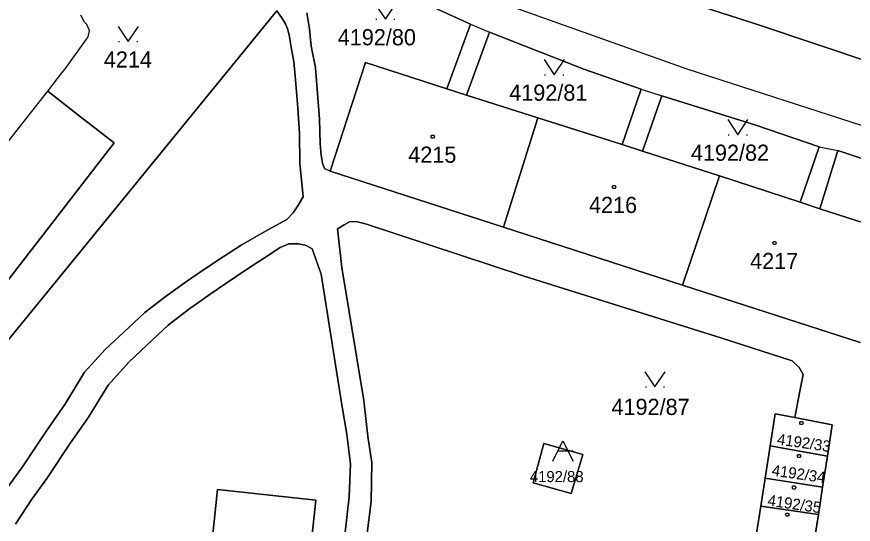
# Model space of a CAD drawing. Extents: x -263587 to -261993, y -1238795 to -1236748.
# Drawn here: x -262969.2 to -262886.4, y -1237670.1 to -1237619.9 of the extents above; entities that cross this region are included whole.
import ezdxf

# ---------------------------------------------------------------- set-up
doc = ezdxf.new("R2010")
doc.units = 0
doc.layers.add('Vrstva 1', color=7, linetype='Continuous')

msp = doc.modelspace()

# ---------------------------------------------------------------- linework, layer by layer
at = {"layer": 'Vrstva 1'}
for p, q in [((-262931.58, -1237617.28), (-262924.29, -1237620.62)), ((-262924.29, -1237620.62), (-262931.58, -1237617.28)), ((-262902.82, -1237625.08), (-262921.39, -1237618.48)), ((-262895.76, -1237620.68), (-262904.4, -1237617.9)), ((-262904.4, -1237617.9), (-262895.76, -1237620.68)), ((-262978.88, -1237662.66), (-262943.44, -1237619.3)), ((-262943.44, -1237619.3), (-262978.88, -1237662.66)), ((-262942.93, -1237620.05), (-262943.44, -1237619.3)), ((-262943.44, -1237619.3), (-262942.93, -1237620.05)), ((-262940.47, -1237619.5), (-262940.21, -1237621.09)), ((-262940.21, -1237621.09), (-262940.47, -1237619.5)), ((-262962.48, -1237620.43), (-262962.83, -1237619.74)), ((-262942.6, -1237620.6), (-262942.93, -1237620.05)), ((-262942.93, -1237620.05), (-262942.6, -1237620.6)), ((-262933.65, -1237620.14), (-262933.55, -1237620.14)), ((-262931.85, -1237620.14), (-262931.75, -1237620.14)), ((-262962.25, -1237620.66), (-262962.48, -1237620.43)), ((-262961.98, -1237621.24), (-262962.25, -1237620.66)), ((-262942.39, -1237621.09), (-262942.6, -1237620.6)), ((-262942.6, -1237620.6), (-262942.39, -1237621.09)), ((-262942.23, -1237621.68), (-262942.39, -1237621.09)), ((-262942.39, -1237621.09), (-262942.23, -1237621.68)), ((-262940.21, -1237621.09), (-262940.03, -1237622.81)), ((-262940.03, -1237622.81), (-262940.21, -1237621.09)), ((-262924.29, -1237620.62), (-262926.63, -1237627)), ((-262926.63, -1237627), (-262924.29, -1237620.62)), ((-262924.29, -1237620.62), (-262922.38, -1237621.41)), ((-262879, -1237626.33), (-262895.76, -1237620.68)), ((-262895.76, -1237620.68), (-262879, -1237626.33)), ((-262964.37, -1237624.99), (-262962.13, -1237621.87)), ((-262962.13, -1237621.87), (-262961.98, -1237621.24)), ((-262942.02, -1237622.93), (-262942.23, -1237621.68)), ((-262942.23, -1237621.68), (-262942.02, -1237622.93)), ((-262924.67, -1237627.63), (-262922.38, -1237621.41)), ((-262922.38, -1237621.41), (-262924.67, -1237627.63)), ((-262922.38, -1237621.41), (-262913.05, -1237625.06)), ((-262913.05, -1237625.06), (-262922.38, -1237621.41)), ((-262959.1, -1237622.34), (-262959, -1237622.34)), ((-262957.3, -1237622.34), (-262957.2, -1237622.34)), ((-262940.03, -1237622.81), (-262939.63, -1237624.94)), ((-262939.63, -1237624.94), (-262940.03, -1237622.81)), ((-262941.76, -1237624.32), (-262942.02, -1237622.93)), ((-262942.02, -1237622.93), (-262941.76, -1237624.32)), ((-262941.63, -1237625.73), (-262941.76, -1237624.32)), ((-262941.76, -1237624.32), (-262941.63, -1237625.73)), ((-262938.16, -1237635.14), (-262934.68, -1237624.42)), ((-262934.68, -1237624.42), (-262938.16, -1237635.14)), ((-262934.68, -1237624.42), (-262926.63, -1237627)), ((-262926.63, -1237627), (-262934.68, -1237624.42)), ((-262964.71, -1237625.42), (-262964.37, -1237624.99)), ((-262939.63, -1237624.94), (-262939.23, -1237630.02)), ((-262939.23, -1237630.02), (-262939.63, -1237624.94)), ((-262913.05, -1237625.06), (-262907.39, -1237627.04)), ((-262907.39, -1237627.04), (-262913.05, -1237625.06)), ((-262860, -1237638.88), (-262902.82, -1237625.08)), ((-262966.1, -1237627.25), (-262964.71, -1237625.42)), ((-262941.36, -1237628.88), (-262941.63, -1237625.73)), ((-262941.63, -1237625.73), (-262941.36, -1237628.88)), ((-262916.94, -1237625.62), (-262916.84, -1237625.62)), ((-262915.14, -1237625.62), (-262915.04, -1237625.62)), ((-262971.93, -1237634.6), (-262966.1, -1237627.25)), ((-262962.88, -1237629.77), (-262966.1, -1237627.25)), ((-262966.1, -1237627.25), (-262962.88, -1237629.77)), ((-262926.63, -1237627), (-262924.67, -1237627.63)), ((-262924.67, -1237627.63), (-262926.63, -1237627)), ((-262924.67, -1237627.63), (-262917.6, -1237629.88)), ((-262917.6, -1237629.88), (-262924.67, -1237627.63)), ((-262907.39, -1237627.04), (-262909.26, -1237632.53)), ((-262909.26, -1237632.53), (-262907.39, -1237627.04)), ((-262907.39, -1237627.04), (-262905.34, -1237627.7)), ((-262907.24, -1237633.16), (-262905.34, -1237627.7)), ((-262905.34, -1237627.7), (-262907.24, -1237633.16)), ((-262905.34, -1237627.7), (-262896.03, -1237630.6)), ((-262896.03, -1237630.6), (-262905.34, -1237627.7)), ((-262941.21, -1237631.43), (-262941.36, -1237628.88)), ((-262941.36, -1237628.88), (-262941.21, -1237631.43)), ((-262962.86, -1237629.77), (-262962.88, -1237629.77)), ((-262962.88, -1237629.77), (-262962.86, -1237629.77)), ((-262960.4, -1237631.69), (-262962.86, -1237629.77)), ((-262962.86, -1237629.77), (-262960.4, -1237631.69)), ((-262939.23, -1237630.02), (-262939.14, -1237632.46)), ((-262939.14, -1237632.46), (-262939.23, -1237630.02)), ((-262921, -1237640.68), (-262917.6, -1237629.88)), ((-262917.6, -1237629.88), (-262921, -1237640.68)), ((-262917.6, -1237629.88), (-262909.26, -1237632.53)), ((-262909.26, -1237632.53), (-262917.6, -1237629.88)), ((-262896.03, -1237630.6), (-262889.77, -1237632.75)), ((-262889.77, -1237632.75), (-262896.03, -1237630.6)), ((-262959.55, -1237632.35), (-262960.4, -1237631.69)), ((-262960.4, -1237631.69), (-262959.55, -1237632.35)), ((-262941.18, -1237634.35), (-262941.21, -1237631.43)), ((-262941.21, -1237631.43), (-262941.18, -1237634.35)), ((-262898.77, -1237631.56), (-262898.67, -1237631.56)), ((-262896.97, -1237631.56), (-262896.87, -1237631.56)), ((-262978.39, -1237656.69), (-262959.55, -1237632.35)), ((-262959.55, -1237632.35), (-262978.39, -1237656.69)), ((-262939.14, -1237632.46), (-262939.06, -1237633.57)), ((-262939.06, -1237633.57), (-262939.14, -1237632.46)), ((-262909.26, -1237632.53), (-262907.24, -1237633.16)), ((-262907.24, -1237633.16), (-262909.26, -1237632.53)), ((-262889.77, -1237632.75), (-262891.65, -1237638.22)), ((-262891.65, -1237638.22), (-262889.77, -1237632.75)), ((-262889.77, -1237632.75), (-262887.91, -1237633.12)), ((-262939.06, -1237633.57), (-262938.93, -1237634.37)), ((-262938.93, -1237634.37), (-262939.06, -1237633.57)), ((-262907.24, -1237633.16), (-262899.64, -1237635.63)), ((-262899.64, -1237635.63), (-262907.24, -1237633.16)), ((-262889.71, -1237638.87), (-262887.91, -1237633.12)), ((-262887.91, -1237633.12), (-262889.71, -1237638.87)), ((-262887.91, -1237633.12), (-262872.56, -1237638.2)), ((-262872.56, -1237638.2), (-262887.91, -1237633.12)), ((-262940.84, -1237637.69), (-262941.18, -1237634.35)), ((-262941.18, -1237634.35), (-262940.84, -1237637.69)), ((-262938.93, -1237634.37), (-262938.74, -1237634.9)), ((-262938.74, -1237634.9), (-262938.93, -1237634.37)), ((-262938.74, -1237634.9), (-262938.16, -1237635.14)), ((-262938.16, -1237635.14), (-262938.74, -1237634.9)), ((-262921, -1237640.68), (-262938.16, -1237635.14)), ((-262938.16, -1237635.14), (-262921, -1237640.68)), ((-262899.64, -1237635.63), (-262903.28, -1237646.41)), ((-262903.28, -1237646.41), (-262899.64, -1237635.63)), ((-262899.64, -1237635.63), (-262891.65, -1237638.22)), ((-262891.65, -1237638.22), (-262899.64, -1237635.63)), ((-262941.38, -1237638.57), (-262940.84, -1237637.69)), ((-262940.84, -1237637.69), (-262941.38, -1237638.57)), ((-262891.65, -1237638.22), (-262889.71, -1237638.87)), ((-262889.71, -1237638.87), (-262891.65, -1237638.22)), ((-262942.44, -1237639.93), (-262941.82, -1237639.27)), ((-262941.82, -1237639.27), (-262942.44, -1237639.93)), ((-262941.82, -1237639.27), (-262941.38, -1237638.57)), ((-262941.38, -1237638.57), (-262941.82, -1237639.27)), ((-262889.71, -1237638.87), (-262882.33, -1237641.25)), ((-262882.33, -1237641.25), (-262889.71, -1237638.87)), ((-262944.56, -1237641.07), (-262942.44, -1237639.93)), ((-262942.44, -1237639.93), (-262944.56, -1237641.07)), ((-262936.77, -1237640.46), (-262936.24, -1237640.16)), ((-262936.24, -1237640.16), (-262936.77, -1237640.46)), ((-262936.24, -1237640.16), (-262935.58, -1237640.12)), ((-262935.58, -1237640.12), (-262936.24, -1237640.16)), ((-262935.58, -1237640.12), (-262934.68, -1237640.37)), ((-262934.68, -1237640.37), (-262935.58, -1237640.12)), ((-262937.43, -1237640.85), (-262936.77, -1237640.46)), ((-262936.77, -1237640.46), (-262937.43, -1237640.85)), ((-262937, -1237644.67), (-262937.43, -1237640.85)), ((-262937.43, -1237640.85), (-262937, -1237644.67)), ((-262934.68, -1237640.37), (-262918.98, -1237645.53)), ((-262918.98, -1237645.53), (-262934.68, -1237640.37)), ((-262903.28, -1237646.41), (-262921, -1237640.68)), ((-262921, -1237640.68), (-262903.28, -1237646.41)), ((-262946.98, -1237642.46), (-262944.56, -1237641.07)), ((-262944.56, -1237641.07), (-262946.98, -1237642.46)), ((-262948.76, -1237643.61), (-262946.98, -1237642.46)), ((-262946.98, -1237642.46), (-262948.76, -1237643.61)), ((-262943.13, -1237642.69), (-262944.66, -1237643.72)), ((-262944.66, -1237643.72), (-262943.13, -1237642.69)), ((-262942.24, -1237642.33), (-262943.13, -1237642.69)), ((-262943.13, -1237642.69), (-262942.24, -1237642.33)), ((-262941.27, -1237642.33), (-262942.24, -1237642.33)), ((-262942.24, -1237642.33), (-262941.27, -1237642.33)), ((-262940.53, -1237642.49), (-262941.27, -1237642.33)), ((-262941.27, -1237642.33), (-262940.53, -1237642.49)), ((-262939.94, -1237642.83), (-262940.53, -1237642.49)), ((-262940.53, -1237642.49), (-262939.94, -1237642.83)), ((-262939.07, -1237645.35), (-262939.94, -1237642.83)), ((-262939.94, -1237642.83), (-262939.07, -1237645.35)), ((-262950.8, -1237644.99), (-262948.76, -1237643.61)), ((-262948.76, -1237643.61), (-262950.8, -1237644.99)), ((-262944.66, -1237643.72), (-262946.44, -1237644.87)), ((-262946.44, -1237644.87), (-262944.66, -1237643.72)), ((-262952.37, -1237646.07), (-262950.8, -1237644.99)), ((-262950.8, -1237644.99), (-262952.37, -1237646.07)), ((-262946.44, -1237644.87), (-262948.48, -1237646.25)), ((-262948.48, -1237646.25), (-262946.44, -1237644.87)), ((-262934.83, -1237657.83), (-262937, -1237644.67)), ((-262937, -1237644.67), (-262934.83, -1237657.83)), ((-262937, -1237658.26), (-262939.07, -1237645.35)), ((-262939.07, -1237645.35), (-262937, -1237658.26)), ((-262918.98, -1237645.53), (-262899.4, -1237651.65)), ((-262899.4, -1237651.65), (-262918.98, -1237645.53)), ((-262954.5, -1237647.58), (-262952.37, -1237646.07)), ((-262952.37, -1237646.07), (-262954.5, -1237647.58)), ((-262948.48, -1237646.25), (-262950.05, -1237647.33)), ((-262950.05, -1237647.33), (-262948.48, -1237646.25)), ((-262885.72, -1237652.08), (-262903.28, -1237646.41)), ((-262903.28, -1237646.41), (-262885.72, -1237652.08)), ((-262956.51, -1237649.12), (-262954.5, -1237647.58)), ((-262954.5, -1237647.58), (-262956.51, -1237649.12)), ((-262950.05, -1237647.33), (-262952.18, -1237648.84)), ((-262952.18, -1237648.84), (-262950.05, -1237647.33)), ((-262958.63, -1237651.09), (-262956.51, -1237649.12)), ((-262956.51, -1237649.12), (-262958.63, -1237651.09)), ((-262952.18, -1237648.84), (-262954.19, -1237650.38)), ((-262954.19, -1237650.38), (-262952.18, -1237648.84)), ((-262954.19, -1237650.38), (-262956.31, -1237652.35)), ((-262956.31, -1237652.35), (-262954.19, -1237650.38)), ((-262960.42, -1237652.79), (-262958.63, -1237651.09)), ((-262958.63, -1237651.09), (-262960.42, -1237652.79)), ((-262899.4, -1237651.65), (-262892.44, -1237653.92)), ((-262892.44, -1237653.92), (-262899.4, -1237651.65)), ((-262956.31, -1237652.35), (-262958.1, -1237654.05)), ((-262958.1, -1237654.05), (-262956.31, -1237652.35)), ((-262962.47, -1237655.04), (-262960.42, -1237652.79)), ((-262960.42, -1237652.79), (-262962.47, -1237655.04)), ((-262958.1, -1237654.05), (-262960.15, -1237656.3)), ((-262960.15, -1237656.3), (-262958.1, -1237654.05)), ((-262892.44, -1237653.92), (-262891.74, -1237654.57)), ((-262891.74, -1237654.57), (-262892.44, -1237653.92)), ((-262964.41, -1237658.21), (-262962.47, -1237655.04)), ((-262962.47, -1237655.04), (-262964.41, -1237658.21)), ((-262891.74, -1237654.57), (-262891.37, -1237655.25)), ((-262891.37, -1237655.25), (-262891.74, -1237654.57)), ((-262891.37, -1237655.25), (-262891.68, -1237656.92)), ((-262891.68, -1237656.92), (-262891.37, -1237655.25)), ((-262960.15, -1237656.3), (-262962.09, -1237659.47)), ((-262962.09, -1237659.47), (-262960.15, -1237656.3)), ((-262906.97, -1237656.48), (-262906.87, -1237656.48)), ((-262905.17, -1237656.48), (-262905.07, -1237656.48)), ((-262891.68, -1237656.92), (-262892.19, -1237659.52)), ((-262892.19, -1237659.52), (-262891.68, -1237656.92)), ((-262966.25, -1237660.84), (-262964.41, -1237658.21)), ((-262964.41, -1237658.21), (-262966.25, -1237660.84)), ((-262936.51, -1237661.16), (-262937, -1237658.26)), ((-262937, -1237658.26), (-262936.51, -1237661.16)), ((-262934.43, -1237661.38), (-262934.83, -1237657.83)), ((-262934.83, -1237657.83), (-262934.43, -1237661.38)), ((-262894.61, -1237662.3), (-262894.11, -1237659.14)), ((-262894.11, -1237659.14), (-262894.61, -1237662.3)), ((-262894.11, -1237659.14), (-262892.19, -1237659.52)), ((-262892.19, -1237659.52), (-262894.11, -1237659.14)), ((-262962.09, -1237659.47), (-262963.93, -1237662.1)), ((-262963.93, -1237662.1), (-262962.09, -1237659.47)), ((-262892.19, -1237659.52), (-262888.49, -1237660.24)), ((-262888.49, -1237660.24), (-262892.19, -1237659.52)), ((-262968.54, -1237664.28), (-262966.25, -1237660.84)), ((-262966.25, -1237660.84), (-262968.54, -1237664.28)), ((-262888.49, -1237660.24), (-262888.96, -1237663.32)), ((-262888.96, -1237663.32), (-262888.49, -1237660.24)), ((-262936.16, -1237664.13), (-262936.51, -1237661.16)), ((-262936.51, -1237661.16), (-262936.16, -1237664.13)), ((-262934.04, -1237663.97), (-262934.43, -1237661.38)), ((-262934.43, -1237661.38), (-262934.04, -1237663.97)), ((-262963.93, -1237662.1), (-262966.22, -1237665.54)), ((-262966.22, -1237665.54), (-262963.93, -1237662.1)), ((-262917.01, -1237662.08), (-262918.08, -1237665.98)), ((-262918.08, -1237665.98), (-262917.01, -1237662.08)), ((-262913.17, -1237663.17), (-262917.01, -1237662.08)), ((-262917.01, -1237662.08), (-262913.17, -1237663.17)), ((-262895.12, -1237665.52), (-262894.61, -1237662.3)), ((-262894.61, -1237662.3), (-262895.12, -1237665.52)), ((-262894.61, -1237662.3), (-262888.96, -1237663.32)), ((-262888.96, -1237663.32), (-262894.61, -1237662.3)), ((-262914.13, -1237662.83), (-262915.63, -1237662.83)), ((-262914.31, -1237667.01), (-262913.17, -1237663.17)), ((-262913.17, -1237663.17), (-262914.31, -1237667.01)), ((-262888.96, -1237663.32), (-262889.44, -1237666.41)), ((-262889.44, -1237666.41), (-262888.96, -1237663.32)), ((-262936.28, -1237667.34), (-262936.16, -1237664.13)), ((-262936.16, -1237664.13), (-262936.28, -1237667.34)), ((-262934.11, -1237667.83), (-262934.04, -1237663.97)), ((-262934.04, -1237663.97), (-262934.11, -1237667.83)), ((-262970, -1237666.31), (-262968.54, -1237664.28)), ((-262968.54, -1237664.28), (-262970, -1237666.31)), ((-262966.22, -1237665.54), (-262967.68, -1237667.57)), ((-262967.68, -1237667.57), (-262966.22, -1237665.54)), ((-262895.55, -1237668.27), (-262895.12, -1237665.52)), ((-262895.12, -1237665.52), (-262895.55, -1237668.27)), ((-262895.12, -1237665.52), (-262889.44, -1237666.41)), ((-262889.44, -1237666.41), (-262895.12, -1237665.52)), ((-262949.31, -1237666.64), (-262951.38, -1237686.3)), ((-262951.38, -1237686.3), (-262949.31, -1237666.64)), ((-262939.57, -1237667.68), (-262949.31, -1237666.64)), ((-262949.31, -1237666.64), (-262939.57, -1237667.68)), ((-262918.08, -1237665.98), (-262914.31, -1237667.01)), ((-262914.31, -1237667.01), (-262918.08, -1237665.98)), ((-262889.44, -1237666.41), (-262889.85, -1237669.09)), ((-262889.85, -1237669.09), (-262889.44, -1237666.41)), ((-262937.11, -1237674.8), (-262936.28, -1237667.34)), ((-262936.28, -1237667.34), (-262937.11, -1237674.8)), ((-262967.68, -1237667.57), (-262969.3, -1237670.06)), ((-262969.3, -1237670.06), (-262967.68, -1237667.57)), ((-262941.67, -1237687.27), (-262939.57, -1237667.68)), ((-262939.57, -1237667.68), (-262941.67, -1237687.27)), ((-262935.17, -1237676.12), (-262934.11, -1237667.83)), ((-262934.11, -1237667.83), (-262935.17, -1237676.12)), ((-262896.01, -1237671.17), (-262895.55, -1237668.27)), ((-262895.55, -1237668.27), (-262896.01, -1237671.17)), ((-262895.55, -1237668.27), (-262889.85, -1237669.09)), ((-262889.85, -1237669.09), (-262895.55, -1237668.27)), ((-262889.85, -1237669.09), (-262890.29, -1237671.96)), ((-262890.29, -1237671.96), (-262889.85, -1237669.09))]:
    msp.add_line(p, q, dxfattribs=at)
for points in [[(-262933.7, -1237618.64), (-262932.7, -1237620.14), (-262931.7, -1237618.64)], [(-262959.15, -1237620.84), (-262958.15, -1237622.34), (-262957.15, -1237620.84)], [(-262916.99, -1237624.12), (-262915.99, -1237625.62), (-262914.99, -1237624.12)], [(-262898.82, -1237630.06), (-262897.82, -1237631.56), (-262896.82, -1237630.06)], [(-262907.02, -1237654.98), (-262906.02, -1237656.48), (-262905.02, -1237654.98)], [(-262916.13, -1237663.83), (-262915.13, -1237661.83), (-262914.13, -1237663.83)]]:
    msp.add_lwpolyline(points, dxfattribs=at)
for points in [[(-262927.93, -1237631.6), (-262927.84, -1237631.75), (-262927.93, -1237631.9), (-262928.11, -1237631.9), (-262928.2, -1237631.75), (-262928.11, -1237631.6)], [(-262910, -1237636.57), (-262909.91, -1237636.72), (-262910, -1237636.87), (-262910.18, -1237636.87), (-262910.27, -1237636.72), (-262910.18, -1237636.57)], [(-262894.1, -1237642.12), (-262894.01, -1237642.27), (-262894.1, -1237642.42), (-262894.28, -1237642.42), (-262894.37, -1237642.27), (-262894.28, -1237642.12)], [(-262891.43, -1237659.91), (-262891.34, -1237660.06), (-262891.43, -1237660.21), (-262891.61, -1237660.21), (-262891.7, -1237660.06), (-262891.61, -1237659.91)], [(-262891.68, -1237663.18), (-262891.59, -1237663.33), (-262891.68, -1237663.48), (-262891.86, -1237663.48), (-262891.95, -1237663.33), (-262891.86, -1237663.18)], [(-262892.16, -1237666.28), (-262892.07, -1237666.43), (-262892.16, -1237666.58), (-262892.34, -1237666.58), (-262892.43, -1237666.43), (-262892.34, -1237666.28)], [(-262892.84, -1237668.98), (-262892.75, -1237669.13), (-262892.84, -1237669.28), (-262893.02, -1237669.28), (-262893.11, -1237669.13), (-262893.02, -1237668.98)]]:
    msp.add_lwpolyline(points, close=True, dxfattribs=at)

# ---------------------------------------------------------------- texts
for s, height, p in [('4192/80', 1.6, (-262937.413, -1237622.71)), ('4214', 1.6, (-262960.564, -1237624.91)), ('4192/81', 1.6, (-262920.445, -1237628.19)), ('4215', 1.6, (-262930.434, -1237634.32)), ('4192/82', 1.6, (-262902.464, -1237634.13)), ('4216', 1.6, (-262912.548, -1237639.29)), ('4217', 1.6, (-262896.604, -1237644.84)), ('4192/87', 1.6, (-262910.324, -1237659.26)), ('4192/88', 1.1, (-262918.404, -1237665.9))]:
    msp.add_text(s, height=height, dxfattribs=at).set_placement(p)
for s, p in [('4192/33', (-262893.989, -1237662.172)), ('4192/34', (-262894.509, -1237665.242)), ('4192/35', (-262894.929, -1237668.222))]:
    msp.add_text(s, height=1.1, rotation=351.85338, dxfattribs=at).set_placement(p)

doc.saveas('drawing.dxf')
